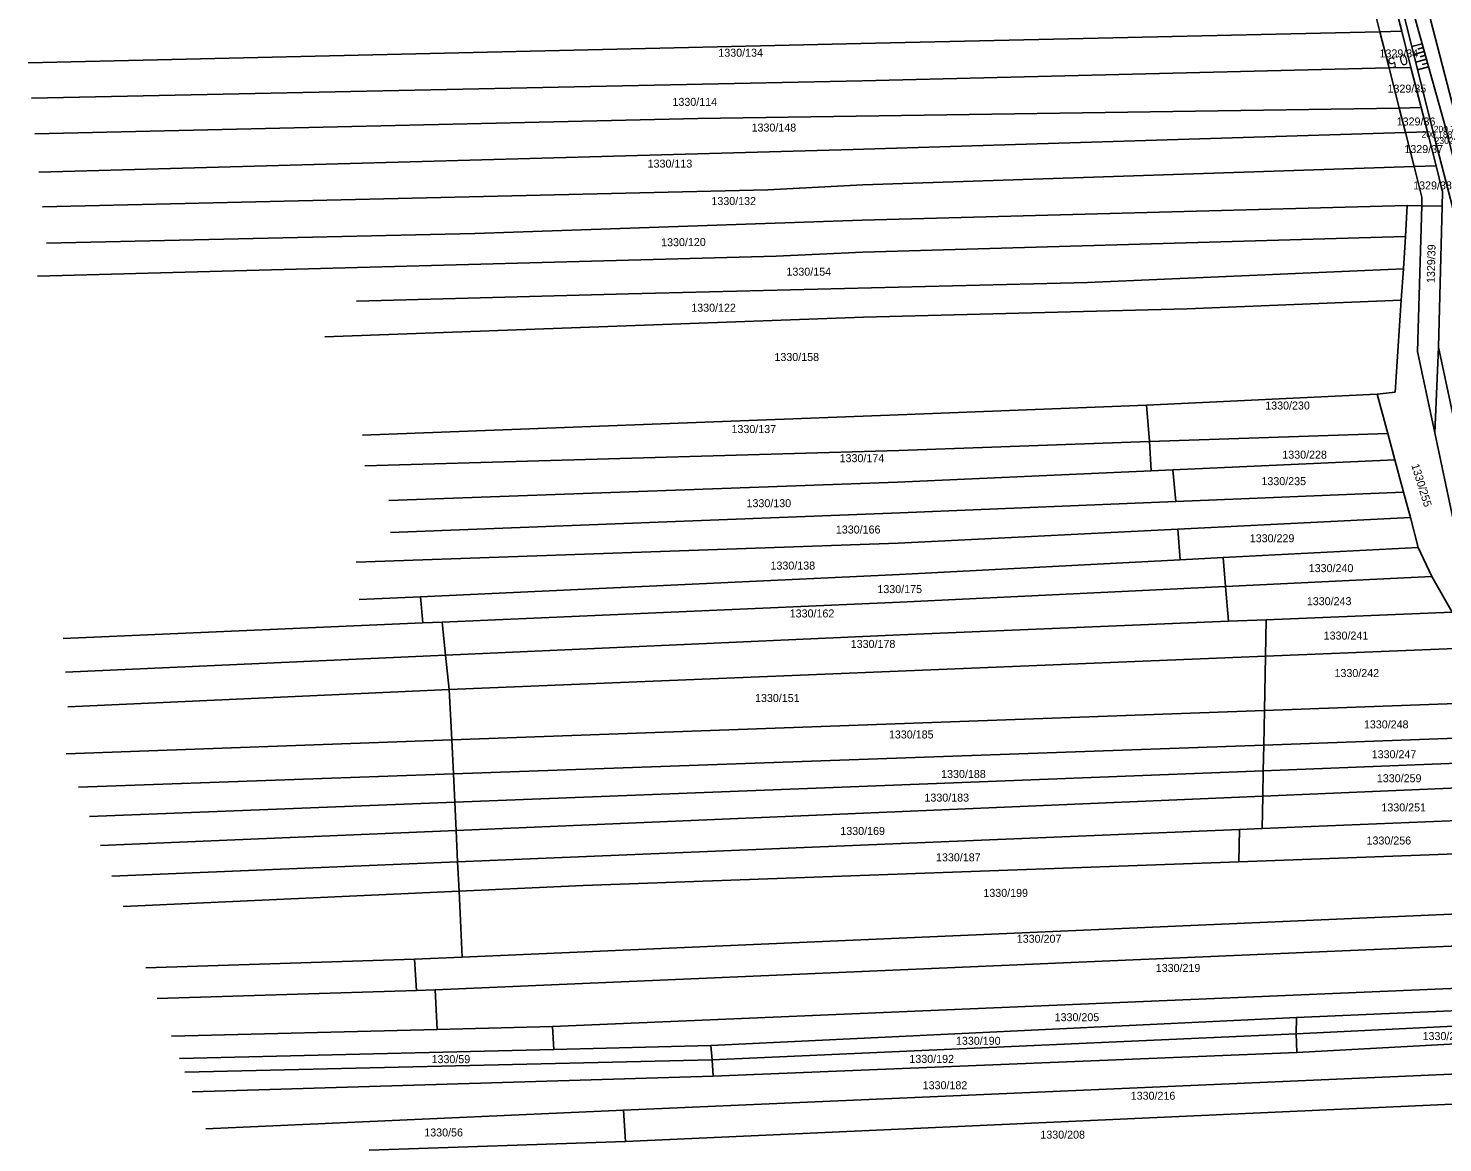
# Model space of a CAD drawing. Extents: x -563148 to -561712, y -1182311 to -1179502.
# Drawn here: x -562697.3 to -562432.1, y -1182097.8 to -1181888.8 of the extents above; entities that cross this region are included whole.
import ezdxf

# ---------------------------------------------------------------- set-up
doc = ezdxf.new("R2010")
doc.units = 0
for name, color, linetype in [('Vrstva 1', 7, 'Continuous'), ('Vrstva 4', 7, 'Continuous'), ('Vrstva 48', 7, 'Continuous'), ('Vrstva 49', 7, 'Continuous'), ('Vrstva 53', 7, 'Continuous'), ('Vrstva 55', 7, 'Continuous'), ('Vrstva 57', 7, 'Continuous'), ('Vrstva 60', 7, 'Continuous'), ('Vrstva 61', 7, 'Continuous')]:
    doc.layers.add(name, color=color, linetype=linetype)

msp = doc.modelspace()

# ---------------------------------------------------------------- linework, layer by layer
at = {"layer": 'Vrstva 1'}
msp.add_lwpolyline([(-562435.35, -1181883.46), (-562429.04, -1181907.88), (-562423.03, -1181931.2), (-562416.86, -1181955.03), (-562409.36, -1181984.04), (-562403.85, -1182005.36), (-562398.01, -1182028.01), (-562391.86, -1182051.88), (-562385.85, -1182075.19), (-562379.55, -1182099.54), (-562373.36, -1182123.49), (-562366.84, -1182148.68), (-562360.83, -1182171.98), (-562354.52, -1182196.41)], dxfattribs=at)
at = {"layer": 'Vrstva 4'}
msp.add_lwpolyline([(-562356.6, -1182197.06), (-562363.67, -1182172.63), (-562369.11, -1182150.39), (-562376, -1182124.38), (-562381.96, -1182100.17), (-562388.24, -1182075.66), (-562394.26, -1182052.53), (-562401.09, -1182025.77), (-562406.12, -1182006.05), (-562411.7, -1181984.7), (-562419.19, -1181956.16), (-562425.49, -1181931.88), (-562431.35, -1181908.29), (-562438.22, -1181883.65), (-562444.12, -1181860.12), (-562450.4, -1181835.43), (-562455.98, -1181813.76), (-562461.84, -1181791.5), (-562470.01, -1181759.75), (-562475.45, -1181735.97), (-562481.27, -1181709.55), (-562485.29, -1181688.62), (-562489.63, -1181662.78), (-562492.85, -1181639.28)], dxfattribs=at)
at = {"layer": 'Vrstva 48'}
for p, q in [((-562435.98, -1181891.69), (-562437.92, -1181892.23)), ((-562435.58, -1181893.14), (-562437.55, -1181893.69)), ((-562435.17, -1181894.58), (-562437.19, -1181895.15)), ((-562435.78, -1181892.42), (-562436.76, -1181892.69)), ((-562435.38, -1181893.86), (-562436.37, -1181894.14)), ((-562434.77, -1181896.03), (-562436.82, -1181896.6)), ((-562434.97, -1181895.31), (-562435.99, -1181895.59))]:
    msp.add_line(p, q, dxfattribs=at)
at = {"layer": 'Vrstva 49'}
for points in [[(-562356.6, -1182197.06), (-562363.67, -1182172.63), (-562369.11, -1182150.39), (-562376, -1182124.38), (-562381.96, -1182100.17), (-562388.24, -1182075.66), (-562394.26, -1182052.53), (-562401.09, -1182025.77), (-562406.12, -1182006.05), (-562411.7, -1181984.7), (-562419.19, -1181956.16), (-562425.49, -1181931.88), (-562431.35, -1181908.29), (-562438.22, -1181883.65), (-562444.12, -1181860.12), (-562450.4, -1181835.43), (-562455.98, -1181813.76), (-562461.84, -1181791.5), (-562470.01, -1181759.75), (-562475.45, -1181735.97), (-562481.27, -1181709.55), (-562485.29, -1181688.62), (-562489.63, -1181662.78), (-562492.85, -1181639.28)], [(-562439.74, -1181884.96), (-562433.65, -1181909.28), (-562427.61, -1181932.66), (-562421.24, -1181957.62), (-562414.26, -1181985.12), (-562408.78, -1182006.67), (-562403.49, -1182026.15), (-562396.95, -1182053.47), (-562390.33, -1182076.35), (-562384.2, -1182100.8), (-562378.1, -1182124.82), (-562372.04, -1182148.77), (-562365.7, -1182172.92), (-562358.85, -1182197.09), (-562356.6, -1182197.06)]]:
    msp.add_lwpolyline(points, dxfattribs=at)
at = {"layer": 'Vrstva 53'}
for p, q in [((-562441.39, -1181883.08), (-562439.8, -1181889.33)), ((-562439.8, -1181889.33), (-562438.08, -1181896.12)), ((-562438.08, -1181896.12), (-562436.16, -1181903.66)), ((-562436.16, -1181903.66), (-562435, -1181908.23)), ((-562435, -1181908.23), (-562433.38, -1181914.57)), ((-562433.38, -1181914.57), (-562432.14, -1181919.46)), ((-562432.21, -1181922.15), (-562432.14, -1181919.46)), ((-562432.92, -1181948.58), (-562432.21, -1181922.15)), ((-562425.54, -1181983.33), (-562432.92, -1181948.58))]:
    msp.add_line(p, q, dxfattribs=at)
at = {"layer": 'Vrstva 55'}
for p, q in [((-562445.5, -1181883.14), (-562443.91, -1181889.43)), ((-562541.23, -1181891.64), (-562443.91, -1181889.43)), ((-562443.91, -1181889.43), (-562439.8, -1181889.33)), ((-562443.91, -1181889.43), (-562442.18, -1181896.22)), ((-562697.3, -1181895.28), (-562541.23, -1181891.64)), ((-562540.97, -1181898.66), (-562442.18, -1181896.22)), ((-562442.18, -1181896.22), (-562438.08, -1181896.12)), ((-562440.27, -1181903.74), (-562442.18, -1181896.22)), ((-562696.7, -1181901.89), (-562540.97, -1181898.66)), ((-562571.8, -1181905.69), (-562440.27, -1181903.74)), ((-562440.27, -1181903.74), (-562436.16, -1181903.66)), ((-562439.1, -1181908.35), (-562440.27, -1181903.74)), ((-562696.09, -1181908.56), (-562571.8, -1181905.69)), ((-562439.1, -1181908.35), (-562435, -1181908.23)), ((-562542.66, -1181911.53), (-562439.1, -1181908.35)), ((-562439.1, -1181908.35), (-562437.48, -1181914.7)), ((-562695.32, -1181915.8), (-562542.66, -1181911.53)), ((-562540.84, -1181918.16), (-562437.48, -1181914.7)), ((-562437.48, -1181914.7), (-562433.38, -1181914.57)), ((-562437.48, -1181914.7), (-562436.02, -1181920.45)), ((-562558.64, -1181919.07), (-562540.84, -1181918.16)), ((-562694.61, -1181922.3), (-562558.64, -1181919.07)), ((-562436.06, -1181922.07), (-562436.02, -1181920.45)), ((-562540.97, -1181924.79), (-562438.78, -1181922.02)), ((-562438.78, -1181922.02), (-562439.1, -1181927.85)), ((-562438.78, -1181922.02), (-562436.06, -1181922.07)), ((-562436.83, -1181949.41), (-562436.06, -1181922.07)), ((-562432.21, -1181922.15), (-562436.06, -1181922.07)), ((-562613.61, -1181927.26), (-562540.97, -1181924.79)), ((-562693.88, -1181929.08), (-562613.61, -1181927.26)), ((-562540.84, -1181930.77), (-562439.1, -1181927.85)), ((-562439.5, -1181933.93), (-562439.1, -1181927.85)), ((-562695.59, -1181935.27), (-562557.08, -1181931.55)), ((-562557.08, -1181931.55), (-562540.84, -1181930.77)), ((-562498.74, -1181936.45), (-562439.5, -1181933.93)), ((-562439.89, -1181939.79), (-562439.5, -1181933.93)), ((-562584.76, -1181938.57), (-562498.74, -1181936.45)), ((-562635.78, -1181939.96), (-562584.76, -1181938.57)), ((-562480.03, -1181941.43), (-562439.89, -1181939.79)), ((-562441.03, -1181957.03), (-562439.89, -1181939.79)), ((-562540.71, -1181942.99), (-562480.03, -1181941.43)), ((-562641.68, -1181946.63), (-562540.71, -1181942.99)), ((-562433.59, -1181964.66), (-562436.83, -1181949.41)), ((-562432.92, -1181948.58), (-562433.59, -1181964.66)), ((-562487.67, -1181959.48), (-562444.41, -1181957.42)), ((-562441.03, -1181957.03), (-562444.41, -1181957.42)), ((-562444.41, -1181957.42), (-562442.43, -1181964.78)), ((-562634.66, -1181965.09), (-562534.21, -1181961.32)), ((-562487.67, -1181959.48), (-562534.21, -1181961.32)), ((-562487.67, -1181959.48), (-562487.11, -1181966.32)), ((-562534.08, -1181967.95), (-562487.11, -1181966.32)), ((-562487.11, -1181966.32), (-562442.43, -1181964.78)), ((-562487.11, -1181966.32), (-562486.8, -1181971.78)), ((-562442.43, -1181964.78), (-562441.1, -1181969.7)), ((-562429.45, -1181984.16), (-562433.59, -1181964.66)), ((-562634.23, -1181970.86), (-562534.08, -1181967.95)), ((-562534.34, -1181973.93), (-562486.8, -1181971.78)), ((-562486.8, -1181971.78), (-562482.7, -1181971.59)), ((-562482.7, -1181971.59), (-562441.1, -1181969.7)), ((-562482.7, -1181971.59), (-562482.17, -1181977.52)), ((-562441.1, -1181969.7), (-562439.47, -1181975.77)), ((-562629.68, -1181977.33), (-562534.34, -1181973.93)), ((-562482.17, -1181977.52), (-562439.47, -1181975.77)), ((-562439.47, -1181975.77), (-562438.18, -1181980.56)), ((-562629.39, -1181983.36), (-562533.82, -1181979.65)), ((-562533.82, -1181979.65), (-562482.17, -1181977.52)), ((-562481.81, -1181982.74), (-562438.18, -1181980.56)), ((-562438.18, -1181980.56), (-562436.75, -1181986.15)), ((-562534.21, -1181985.37), (-562481.81, -1181982.74)), ((-562481.81, -1181982.74), (-562481.37, -1181988.48)), ((-562635.86, -1181988.93), (-562534.21, -1181985.37)), ((-562473.26, -1181988.05), (-562436.75, -1181986.15)), ((-562436.75, -1181986.15), (-562434.15, -1181991.61)), ((-562533.95, -1181991.22), (-562481.37, -1181988.48)), ((-562481.37, -1181988.48), (-562473.26, -1181988.05)), ((-562473.26, -1181988.05), (-562472.82, -1181993.48)), ((-562623.77, -1181995.4), (-562533.95, -1181991.22)), ((-562472.82, -1181993.48), (-562434.15, -1181991.61)), ((-562434.15, -1181991.61), (-562430.38, -1181998.32)), ((-562635.24, -1181995.94), (-562623.77, -1181995.4)), ((-562623.77, -1181995.4), (-562623.36, -1182000.31)), ((-562533.82, -1181996.42), (-562472.82, -1181993.48)), ((-562472.82, -1181993.48), (-562472.28, -1182000.02)), ((-562619.73, -1182000.15), (-562533.82, -1181996.42)), ((-562465.25, -1181999.74), (-562430.38, -1181998.32)), ((-562690.74, -1182003.24), (-562623.36, -1182000.31)), ((-562623.36, -1182000.31), (-562619.73, -1182000.15)), ((-562619.73, -1182000.15), (-562619.06, -1182006.37)), ((-562533.82, -1182002.53), (-562472.28, -1182000.02)), ((-562472.28, -1182000.02), (-562465.25, -1181999.74)), ((-562465.37, -1182006.55), (-562465.25, -1181999.74)), ((-562619.06, -1182006.37), (-562533.82, -1182002.53)), ((-562690.33, -1182009.58), (-562619.06, -1182006.37)), ((-562619.06, -1182006.37), (-562618.38, -1182012.78)), ((-562426.64, -1182004.97), (-562465.37, -1182006.55)), ((-562465.37, -1182006.55), (-562618.38, -1182012.78)), ((-562465.56, -1182016.72), (-562465.37, -1182006.55)), ((-562689.91, -1182016.08), (-562618.38, -1182012.78)), ((-562618.38, -1182012.78), (-562617.92, -1182022.27)), ((-562617.92, -1182022.27), (-562465.56, -1182016.72)), ((-562465.68, -1182023.24), (-562465.56, -1182016.72)), ((-562465.56, -1182016.72), (-562420.94, -1182015.09)), ((-562690.18, -1182024.9), (-562617.92, -1182022.27)), ((-562617.92, -1182022.27), (-562617.61, -1182028.64)), ((-562465.68, -1182023.24), (-562417.31, -1182021.52)), ((-562617.61, -1182028.64), (-562465.68, -1182023.24)), ((-562465.76, -1182028.04), (-562465.68, -1182023.24)), ((-562465.76, -1182028.04), (-562415.82, -1182026.1)), ((-562687.86, -1182031.13), (-562617.61, -1182028.64)), ((-562617.61, -1182028.64), (-562617.35, -1182033.95)), ((-562617.35, -1182033.95), (-562465.76, -1182028.04)), ((-562465.85, -1182032.79), (-562465.76, -1182028.04)), ((-562617.1, -1182039.25), (-562465.85, -1182032.79)), ((-562465.96, -1182038.87), (-562465.85, -1182032.79)), ((-562465.85, -1182032.79), (-562414.36, -1182030.59)), ((-562685.82, -1182036.62), (-562617.35, -1182033.95)), ((-562617.35, -1182033.95), (-562617.1, -1182039.25)), ((-562465.96, -1182038.87), (-562412.4, -1182036.65)), ((-562683.78, -1182042.09), (-562617.1, -1182039.25)), ((-562617.1, -1182039.25), (-562616.81, -1182045.14)), ((-562616.81, -1182045.14), (-562470.24, -1182039.05)), ((-562470.24, -1182039.05), (-562470.32, -1182045.11)), ((-562470.24, -1182039.05), (-562465.96, -1182038.87)), ((-562470.32, -1182045.11), (-562410.36, -1182042.92)), ((-562681.64, -1182047.83), (-562616.81, -1182045.14)), ((-562616.81, -1182045.14), (-562616.54, -1182050.66)), ((-562593.26, -1182049.6), (-562470.32, -1182045.11)), ((-562679.53, -1182053.53), (-562616.54, -1182050.66)), ((-562616.54, -1182050.66), (-562593.26, -1182049.6)), ((-562616.54, -1182050.66), (-562615.94, -1182063.02)), ((-562615.94, -1182063.02), (-562406.79, -1182053.92)), ((-562621.03, -1182069.13), (-562404.86, -1182059.85)), ((-562675.25, -1182065.02), (-562624.92, -1182063.41)), ((-562624.92, -1182063.41), (-562615.94, -1182063.02)), ((-562624.53, -1182069.28), (-562624.92, -1182063.41)), ((-562673.12, -1182070.76), (-562624.53, -1182069.28)), ((-562624.53, -1182069.28), (-562621.03, -1182069.13)), ((-562621.03, -1182069.13), (-562620.66, -1182076.56)), ((-562599.04, -1182076), (-562402.31, -1182067.71)), ((-562459.51, -1182074.32), (-562400.96, -1182071.85)), ((-562569.32, -1182079.55), (-562459.51, -1182074.32)), ((-562459.6, -1182077.36), (-562459.51, -1182074.32)), ((-562459.6, -1182077.36), (-562400.1, -1182074.5)), ((-562670.48, -1182077.85), (-562620.66, -1182076.56)), ((-562620.66, -1182076.56), (-562599.04, -1182076)), ((-562598.79, -1182080.31), (-562599.04, -1182076)), ((-562569.07, -1182082.29), (-562459.6, -1182077.36)), ((-562459.47, -1182080.88), (-562459.6, -1182077.36)), ((-562459.47, -1182080.88), (-562399.09, -1182077.62)), ((-562668.93, -1182082.01), (-562598.79, -1182080.31)), ((-562598.79, -1182080.31), (-562569.32, -1182079.55)), ((-562569.07, -1182082.29), (-562569.32, -1182079.55)), ((-562667.97, -1182084.61), (-562569.07, -1182082.29)), ((-562568.9, -1182085.31), (-562569.07, -1182082.29)), ((-562568.9, -1182085.31), (-562459.47, -1182080.88)), ((-562666.6, -1182088.28), (-562568.9, -1182085.31)), ((-562585.71, -1182091.7), (-562397.17, -1182083.52)), ((-562585.31, -1182097.56), (-562395.38, -1182089.04)), ((-562664.03, -1182095.2), (-562585.71, -1182091.7)), ((-562585.31, -1182097.56), (-562585.71, -1182091.7)), ((-562633.38, -1182099.22), (-562585.31, -1182097.56))]:
    msp.add_line(p, q, dxfattribs=at)
at = {"layer": 'Vrstva 60'}
msp.add_line((-562433.65, -1181909.28), (-562433.65, -1181909.28), dxfattribs=at)

# ---------------------------------------------------------------- texts
at = {"layer": 'Vrstva 48'}
msp.add_text('0,5', height=2, rotation=194.0712, dxfattribs=at).set_placement((-562438.97, -1181893.56))
at = {"layer": 'Vrstva 57'}
for s, p in [('1330/134', (-562567.93, -1181894.12)), ('1329/34', (-562443.98, -1181894.25)), ('1329/35', (-562442.47, -1181900.85)), ('1330/114', (-562576.53, -1181903.34)), ('1329/36', (-562440.75, -1181907.02)), ('1330/148', (-562561.7, -1181908.16)), ('1329/37', (-562439.31, -1181912.19)), ('1330/113', (-562581.19, -1181914.92)), ('1329/38', (-562437.66, -1181919.01)), ('1330/132', (-562569.23, -1181921.94)), ('1330/154', (-562555.16, -1181935.19)), ('1330/122', (-562573.01, -1181941.95)), ('1330/158', (-562557.41, -1181951.19)), ('1330/230', (-562465.4, -1181960.29)), ('1330/137', (-562565.46, -1181964.71)), ('1330/174', (-562545.19, -1181970.17)), ('1330/228', (-562462.2, -1181969.51)), ('1330/235', (-562466.11, -1181974.48)), ('1330/130', (-562562.65, -1181978.61)), ('1330/166', (-562545.9, -1181983.55)), ('1330/229', (-562468.3, -1181985.19)), ('1330/138', (-562558.15, -1181990.31)), ('1330/240', (-562457.24, -1181990.79)), ('1330/175', (-562538.11, -1181994.73)), ('1330/243', (-562457.6, -1181996.99)), ('1330/162', (-562554.55, -1181999.29)), ('1330/178', (-562543.11, -1182005.01)), ('1330/241', (-562454.44, -1182003.44)), ('1330/242', (-562452.41, -1182010.47)), ('1330/151', (-562561.05, -1182015.15)), ('1330/248', (-562446.9, -1182020.1)), ('1330/185', (-562535.95, -1182021.99)), ('1330/247', (-562445.44, -1182025.7)), ('1330/188', (-562526.16, -1182029.4)), ('1330/259', (-562444.47, -1182030.2)), ('1330/183', (-562529.29, -1182033.83)), ('1330/251', (-562443.62, -1182035.68)), ('1330/169', (-562545.06, -1182040.09)), ('1330/256', (-562446.41, -1182041.88)), ('1330/187', (-562527.12, -1182045.04)), ('1330/199', (-562518.24, -1182051.7)), ('1330/207', (-562511.98, -1182060.31)), ('1330/219', (-562485.93, -1182065.78)), ('1330/205', (-562504.88, -1182075.02)), ('1330/190', (-562523.38, -1182079.45)), ('1330/250', (-562435.9, -1182078.56)), ('1330/59', (-562621.7, -1182082.89)), ('1330/192', (-562532.11, -1182082.84)), ('1330/182', (-562529.62, -1182087.78)), ('1330/216', (-562490.62, -1182089.75)), ('1330/56', (-562623.06, -1182096.64)), ('1330/208', (-562507.56, -1182097.05))]:
    msp.add_text(s, height=1.5, dxfattribs=at).set_placement(p)
for s, rotation, p in [('1330/120', 0.4385, (-562578.65, -1181929.68)), ('1329/39', 88.5797, (-562433.63, -1181936.59)), ('1330/255', 287.1646, (-562438.03, -1181970.72))]:
    msp.add_text(s, height=1.5, rotation=rotation, dxfattribs=at).set_placement(p)
at = {"layer": 'Vrstva 60'}
msp.add_text('230200010290', height=1.2, dxfattribs=at).set_placement((-562433.65, -1181910.48))
at = {"layer": 'Vrstva 61'}
for s, p in [('200.188', (-562436.1, -1181909.28)), ('200.758', (-562433.81, -1181908.29))]:
    msp.add_text(s, height=1.2, dxfattribs=at).set_placement(p)

doc.saveas('drawing.dxf')
